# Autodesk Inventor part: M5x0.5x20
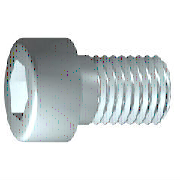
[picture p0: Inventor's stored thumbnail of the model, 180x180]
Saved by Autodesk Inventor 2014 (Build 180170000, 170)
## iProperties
IsCustomPart: 0
Company: 한국ATC센터
Created: 2009-02
Part Number: M5x0.5x20
Material: Steel, Mild
Description: 6각머리 태핑 나사
Document SubType Name: Modeling
Standard: KS B 1003
Designer: KYOUNG IL JANG
Standards Organization: KS
Language: ko-KR
Size Designation: M 5 x 20
Categories: <MemberInstance><Categories><Category DisplayName="조임쇠" InternalName="e4da775c-781d-43d5-af7c-5136215cf5a6" Mnemonic="FSTN"><Category DisplayName="볼트" InternalN
Density: 7.86 g/cm^3
Mass: 4.9629 g
Surface Area: 5.88237 cm^2
Volume: 0.631412 cm^3
Appearance: Metal-Steel
Author: KYOUNG IL JANG
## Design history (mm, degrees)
sketch "스케치1"
  geometry: L1 (-1.167, 0)-(20, 0); L2 (20, 0)-(20, 2.5); L3 (20, 2.5)-(2, 2.5); L4 (2, 2.5)-(1.509, 2.5); L5 (1.509, 2.5)-(0, 2.5); L6 (0, 2.5)-(0, 4.25); L7 (0, 4.25)-(-5, 4.25); L8 (-5, 4.25)-(-5, 2.309); L9 (-5, 2.309)-(-2.5, 2.309); L10 (-2.5, 2.309)-(-1.167, 0); L11 (-10, 0)-(25, 0) reference; L12 (0, -0.85)-(0, 5.1) reference; L13 (2, 2.5)-(0, 2.5)
  constraints: 22 end point, 6 parallel, 2 collinear, 2 perpendicular, 1 horizontal, 1 point on line
  dimensions: "d1" = 18 distance from line of L3.end L2 (= GEL); "d2" = 0.49086 distance of L4.end L3.end (computed from GAL); "d3" = 5 distance between parallel lines of L8 L6 (= KOH); "d4" = 2.5 distance of L8.end L9.end (= INTI); "d5" = 60 deg angle of L10 L1; "d6" = 5 diameter of L3 L1 (= GD); "d7" = 5 diameter of L5 L1 (= BDM); "d8" = 4.6188 diameter of L9 L1 (= 1.1547 x SW); "d9" = 8.5 diameter of L7 L1 (= KOD); "d26" = 20 distance between parallel lines of L12 L2 (= NLG)
revolve "본체" sketch "스케치1" stored, may be unused: angle "d10" = 90 deg
sketch "스케치2"
  geometry: L1 (0, -5.95)-(0, 5.95) reference; L2 (-5.95, 0)-(5.95, 0) reference; L3 (2.309, 0)-(1.155, -2); L4 (1.155, -2)-(-1.155, -2); L5 (-1.155, -2)-(-2.309, 0); L6 (-2.309, 0)-(-1.155, 2); L7 (-1.155, 2)-(1.155, 2); L8 (1.155, 2)-(2.309, 0); 2 further points
  constraints: 12 end point, 1 coincident, 1 horizontal alignment, 1 point on line, 12 other
extrude "슬롯" join sketch "스케치2" stored distance "d11" = 10; taper "d12" = 0 deg
workplane "Work Plane1"
fillet "Fillet2" dims "d30" = 0.1 (= R)
body "Solid1"
fillet "모깎기1" dims "d17" = 0.5 (= RR)
feature "스레드" dims "d13" = 18 (= GEL), "d14" = 0
chamfer "모따기1" distance "d15" = 0.49076 (= -0.5 x SPD + 0.5 x GD); stored, may be unused: second distance "d16" = 0.49076 (= GUL), angle "d27" = 45 deg
other parameters: "GD" = 5 (= NND) [user parameter; used in 2 equation terms], "NLG" = 20 [user parameter; used in 1 equation term], "GEL" = 18 [user parameter; used in 2 equation terms], "KOD" = 8.5 [user parameter; used in 1 equation term], "KOH" = 5 [user parameter; used in 1 equation term], "INTI" = 2.5 [user parameter; used in 1 equation term], "GAL" = 0.49076 (= 0.61345 x PTC) [user parameter; used in 1 equation term], "GUL" = 0.49076 (= 0.61345 x PTC) [user parameter; used in 1 equation term], "BDM" = 5 (= NND) [user parameter; used in 1 equation term], "SW" = 4 [user parameter; used in 2 equation terms], "RR" = 0.5 [user parameter; used in 1 equation term], "SPD" = 4.01848 (= NND - 1.2269 x PTC) [user parameter; used in 1 equation term], "d19" = 0, "d28" = 0, "d29" = 0, "R" = 0.1 [user parameter; used in 1 equation term], "PHH" = 0.2 [user parameter], "GD1" = 4.01848 (= THREADDIA - 1.2269 x PTC) [user parameter], "THREADDIA" = 5 [user parameter; used in 1 equation term], "FAWI" = 45 deg [user parameter], "TPU" = 12.5 (computed from PTC) [user parameter], "PTC" = 0.8 [user parameter; used in 5 equation terms], "NND" = 5 [user parameter; used in 3 equation terms], "TOA" = 30 deg [user parameter], "E0" = 4.62 (= 1.155 x SW) [user parameter]
